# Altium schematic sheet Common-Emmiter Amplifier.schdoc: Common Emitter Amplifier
size A4; Organization: Altium Limited; Address1: L3, 12a Rodborough Rd; Address2: Frenchs Forest; Address3: NSW; Address4: Australia 2086; DocumentNumber: 1; SheetNumber: 1; SheetTotal: 1
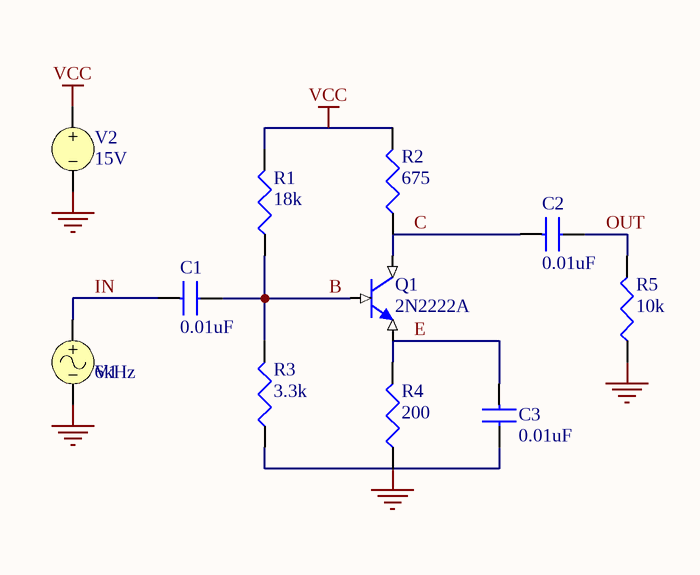
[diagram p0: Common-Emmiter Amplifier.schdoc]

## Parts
C1  0.01uF
C2  0.01uF
C3  0.01uF
Q1  2N2222A
R1  18k
R2  675
R3  3.3k
R4  200
R5  10k
V1  6kHz
V2  15V

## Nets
GND: C3.2 R3.2(BOT) R4.2(BOT) R5.2(BOT) V1.2 V2.2
VCC: R1.1(TOP) R2.1(TOP) V2.1
B: C1.2 Q1.2(B) R1.2(BOT) R3.1(TOP)
C: C2.1 Q1.1(C) R2.2(BOT)
E: C3.1 Q1.3(E) R4.1(TOP)
IN: C1.1 V1.1
OUT: C2.2 R5.1(TOP)

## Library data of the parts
C1-C3 = CAP: Capacitor
Q1 = 2N2222A: NPN BJT
R1-R5 = RES: Resistor
V1 = VSIN: Sinusoidal Voltage Source
V2 = VSRC: Voltage Source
